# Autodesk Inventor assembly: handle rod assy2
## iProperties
Author: Elise Moss
Created: 2001-09
Part Number: handle rod assy2
Document SubType Name: Assembly
Designer: Elise Moss
Control State: 0
Master: False
Checked Out: False
PropertySet Name: Design Tracking Control
Shininess: 64.0
Angle Display Precision: 2
Document Length Units: 11272
Document Angle Units: 11286
Document Time Units: 11279
Document Mass Units: 11290
Document Length Units Precision: 3
Document Angle Units Precision: 2
Compacted: False
PropertySet Name: _Private Model Information
Density: 0.0
Volumn: 0.0
Area: 0.0
PropertySet Name: Model Information
